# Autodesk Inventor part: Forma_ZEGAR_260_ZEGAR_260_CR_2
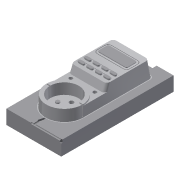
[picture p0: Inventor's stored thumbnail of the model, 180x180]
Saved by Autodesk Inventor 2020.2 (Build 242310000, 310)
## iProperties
Created: 2015-01
Part Number: Forma_ZEGAR_260_ZEGAR_260_CR_2
Material: Ogólny
Document SubType Name: Modeling
Designer: F.Stasiak
Density: 1 g/cm^3
Appearance: Domyślna
Catalog Web Link: www.expertbooks.pl
Manager: www.cadconsulting.pl
Company: Fabian Stasiak CAD Consulting
Author: F.Stasiak
Subject: Zbiór ćwiczeń. Autodesk Inventor 2020. Kurs Professional
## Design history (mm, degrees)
node "Forma_ZEGAR_260_ZEGAR_260_CR_Base"
feature "Rzeźbienie3"
feature "Bryła5::Forma_ZEGAR_260_ZEGAR_260_CR_Base"
tag "Bryła wyprowadzona1"
node "Bryła1"
feature "Forma_ZEGAR_260_ZEGAR_260_CR_Base_Bodies"
feature "Powierzchnia3"
body "Srf3"
